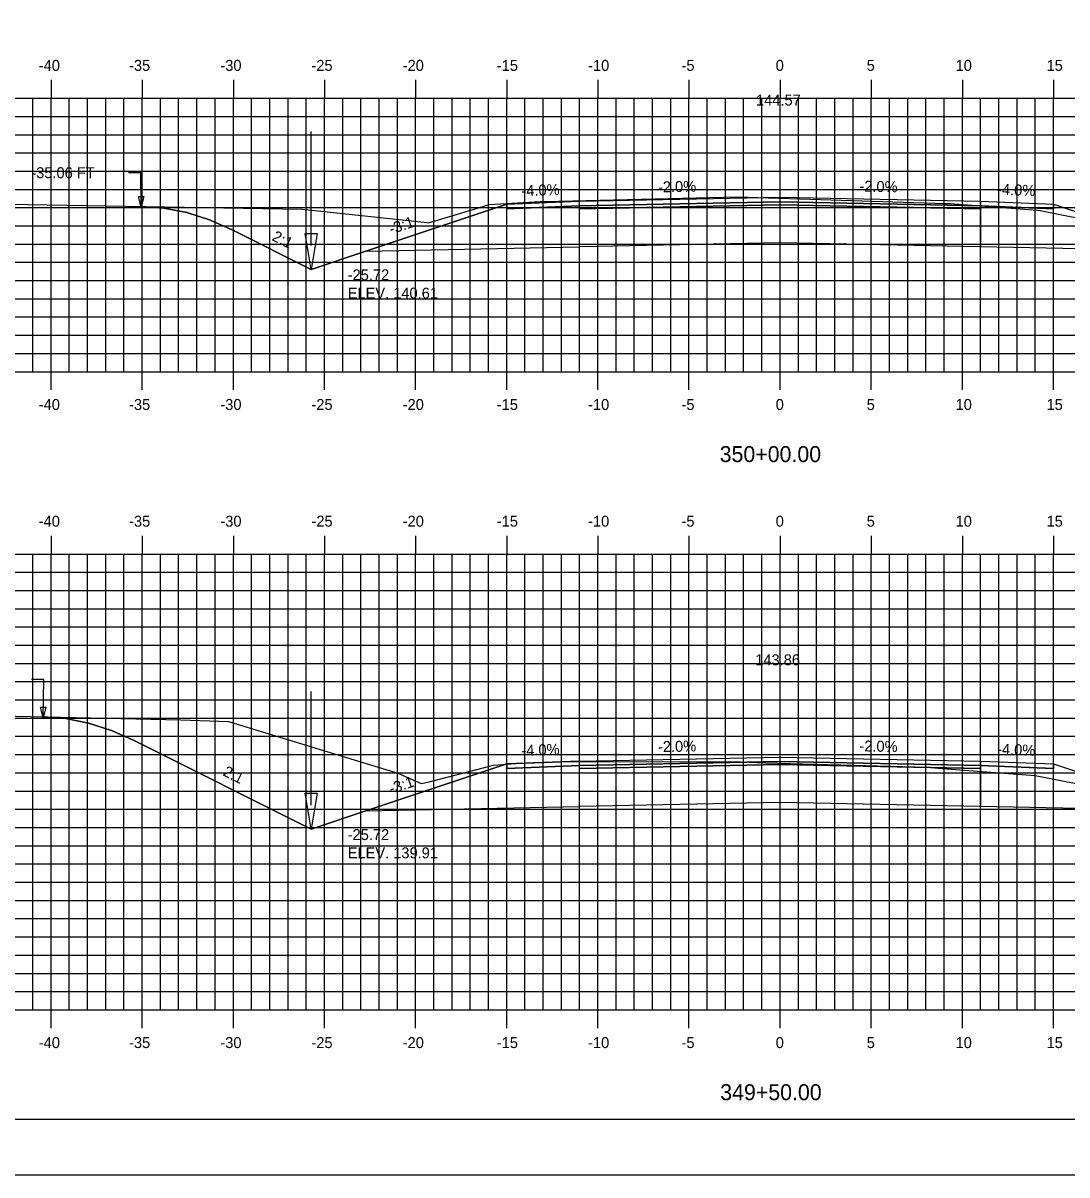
# Model space of a CAD drawing. Extents: x 1144529 to 1144699, y 608981 to 609091.
# Drawn here: x 1144570.3 to 1144627.6, y 608981.3 to 609044.5 of the extents above; entities that cross this region are included whole.
import ezdxf

# ---------------------------------------------------------------- set-up
doc = ezdxf.new("R2010")
doc.units = 0
for name, color, linetype in [('ANNOTATION', 7, 'Continuous'), ('BORDER', 7, 'Continuous'), ('D_Drainage_Ditch_Line', 7, 'Continuous'), ('D_Roadway_Centerline', 7, 'Continuous'), ('D_Roadway_Centerline_Text', 7, 'Continuous'), ('D_Roadway_Edge_Shoulder', 7, 'Continuous'), ('D_Roadway_Edge_TW', 7, 'Continuous'), ('D_Roadway_Pavement', 7, 'Continuous'), ('D_Roadway_SlopeLines', 7, 'Continuous'), ('D_Roadway_SubGrade', 7, 'Continuous'), ('D_Text_Standard', 7, 'Continuous'), ('H_V ANNOTATION', 7, 'Continuous'), ('MAJOR', 7, 'Continuous'), ('MINOR', 7, 'Continuous'), ('PLOT BOUNDARY', 7, 'Continuous'), ('S_Roadway_Centerline', 7, 'Continuous')]:
    doc.layers.add(name, color=color, linetype=linetype)

msp = doc.modelspace()

# ---------------------------------------------------------------- linework, layer by layer
for points in [[(1144576.807, 609034.403), (1144578.057, 609034.307), (1144579.307, 609034.059), (1144580.557, 609033.661), (1144581.807, 609033.112), (1144586.138, 609030.946), (1144589.138, 609031.946), (1144596.861, 609034.521), (1144596.862, 609034.521), (1144600.862, 609034.681), (1144611.862, 609034.901), (1144622.862, 609034.681), (1144626.862, 609034.521), (1144634.586, 609031.946), (1144637.586, 609030.946), (1144639.82, 609032.063), (1144641.07, 609032.601), (1144642.32, 609032.963), (1144643.57, 609033.15), (1144644.82, 609033.162)], [(1144571.423, 609006.407), (1144572.673, 609006.305), (1144573.923, 609006.053), (1144575.173, 609005.652), (1144576.423, 609005.102), (1144586.138, 609000.245), (1144589.138, 609001.245), (1144596.861, 609003.819), (1144596.862, 609003.819), (1144600.862, 609003.979), (1144611.862, 609004.199), (1144622.862, 609003.979), (1144626.862, 609003.819), (1144634.586, 609001.245), (1144637.586, 609000.245), (1144641.379, 609002.141), (1144642.629, 609002.679), (1144643.879, 609003.044), (1144645.129, 609003.234), (1144646.379, 609003.251)]]:
    msp.add_lwpolyline(points)
at = {"layer": 'BORDER'}
msp.add_lwpolyline([(1144536.863, 608984.335), (1144696.863, 608984.335), (1144696.863, 609089.335), (1144536.863, 609089.335)], close=True, dxfattribs=at)
at = {"layer": 'D_Drainage_Ditch_Line'}
for p, q in [((1144586.138, 609032.259), (1144586.138, 609038.502)), ((1144586.138, 609001.557), (1144586.138, 609007.801))]:
    msp.add_line(p, q, dxfattribs=at)
for points in [[(1144585.81, 609032.915), (1144586.466, 609032.915), (1144586.138, 609030.946)], [(1144585.81, 609002.213), (1144586.466, 609002.213), (1144586.138, 609000.245)]]:
    msp.add_lwpolyline(points, close=True, dxfattribs=at)
at = {"layer": 'D_Roadway_Edge_Shoulder'}
for points in [[(1144600.862, 609034.681), (1144596.862, 609034.521), (1144596.862, 609034.271), (1144600.862, 609034.431)], [(1144622.862, 609034.681), (1144626.862, 609034.521), (1144626.862, 609034.271), (1144622.862, 609034.431)], [(1144600.862, 609003.979), (1144596.862, 609003.819), (1144596.862, 609003.569), (1144600.862, 609003.729)], [(1144622.862, 609003.979), (1144626.862, 609003.819), (1144626.862, 609003.569), (1144622.862, 609003.729)]]:
    msp.add_lwpolyline(points, close=True, dxfattribs=at)
at = {"layer": 'D_Roadway_Edge_TW'}
for points in [[(1144600.862, 609034.431), (1144600.862, 609034.681), (1144611.862, 609034.901), (1144622.862, 609034.681), (1144622.862, 609034.431), (1144611.862, 609034.651)], [(1144600.862, 609003.729), (1144600.862, 609003.979), (1144611.862, 609004.199), (1144622.862, 609003.979), (1144622.862, 609003.729), (1144611.862, 609003.949)]]:
    msp.add_lwpolyline(points, close=True, dxfattribs=at)
at = {"layer": 'D_Roadway_Pavement'}
for points in [[(1144600.862, 609034.264), (1144600.862, 609034.431), (1144611.862, 609034.651), (1144622.862, 609034.431), (1144622.862, 609034.264), (1144611.862, 609034.484)], [(1144600.862, 609003.563), (1144600.862, 609003.729), (1144611.862, 609003.949), (1144622.862, 609003.729), (1144622.862, 609003.563), (1144611.862, 609003.783)]]:
    msp.add_lwpolyline(points, close=True, dxfattribs=at)
at = {"layer": 'D_Roadway_SlopeLines'}
for points in [[(1144586.138, 609030.946), (1144581.807, 609033.112), (1144580.557, 609033.661), (1144579.307, 609034.059), (1144578.057, 609034.307), (1144576.807, 609034.403)], [(1144589.138, 609031.946), (1144586.138, 609030.946)], [(1144586.138, 609000.245), (1144576.423, 609005.102), (1144575.173, 609005.652), (1144573.923, 609006.053), (1144572.673, 609006.305), (1144571.423, 609006.407)], [(1144589.138, 609001.245), (1144586.138, 609000.245)]]:
    msp.add_lwpolyline(points, dxfattribs=at)
at = {"layer": 'D_Roadway_SubGrade'}
for points in [[(1144600.862, 609034.264), (1144600.862, 609034.431), (1144596.862, 609034.271), (1144596.862, 609034.521), (1144596.861, 609034.521), (1144589.138, 609031.946), (1144600.862, 609032.181)], [(1144600.862, 609032.181), (1144600.862, 609034.264), (1144611.862, 609034.484), (1144622.862, 609034.264), (1144622.862, 609032.181), (1144611.862, 609032.401)], [(1144622.862, 609034.264), (1144622.862, 609034.431), (1144626.862, 609034.271), (1144626.862, 609034.521), (1144626.862, 609034.521), (1144634.586, 609031.946), (1144622.862, 609032.181)], [(1144600.862, 609003.563), (1144600.862, 609003.729), (1144596.862, 609003.569), (1144596.862, 609003.819), (1144596.861, 609003.819), (1144589.138, 609001.245), (1144600.862, 609001.479)], [(1144600.862, 609001.479), (1144600.862, 609003.563), (1144611.862, 609003.783), (1144622.862, 609003.563), (1144622.862, 609001.479), (1144611.862, 609001.699)], [(1144622.862, 609003.563), (1144622.862, 609003.729), (1144626.862, 609003.569), (1144626.862, 609003.819), (1144626.862, 609003.819), (1144634.586, 609001.245), (1144622.862, 609001.479)]]:
    msp.add_lwpolyline(points, close=True, dxfattribs=at)
at = {"layer": 'D_Text_Standard'}
for points in [[(1144576.807, 609034.362), (1144576.784, 609036.248), (1144576.104, 609036.248)], [(1144571.423, 609006.352), (1144571.464, 609008.455), (1144570.784, 609008.455)]]:
    msp.add_lwpolyline(points, dxfattribs=at)
for points in [[(1144576.807, 609034.362), (1144576.654, 609034.942), (1144576.945, 609034.945)], [(1144571.423, 609006.352), (1144571.289, 609006.937), (1144571.58, 609006.931)]]:
    msp.add_lwpolyline(points, close=True, dxfattribs=at)
at = {"layer": 'MAJOR'}
for p, q in [((1144571.862, 609041.337), (1144571.862, 609040.335)), ((1144576.862, 609041.337), (1144576.862, 609040.335)), ((1144581.862, 609041.337), (1144581.862, 609040.335)), ((1144586.862, 609041.337), (1144586.862, 609040.335)), ((1144591.862, 609041.337), (1144591.862, 609040.335)), ((1144596.862, 609041.337), (1144596.862, 609040.335)), ((1144601.862, 609041.337), (1144601.862, 609040.335)), ((1144606.862, 609041.337), (1144606.862, 609040.335)), ((1144611.862, 609041.337), (1144611.862, 609040.335)), ((1144616.862, 609041.337), (1144616.862, 609040.335)), ((1144621.862, 609041.337), (1144621.862, 609040.335)), ((1144626.862, 609041.337), (1144626.862, 609040.335)), ((1144541.862, 609040.335), (1144681.862, 609040.335)), ((1144541.862, 609040.335), (1144681.862, 609040.335)), ((1144571.862, 609025.335), (1144571.862, 609040.335)), ((1144576.862, 609025.335), (1144576.862, 609040.335)), ((1144581.862, 609025.335), (1144581.862, 609040.335)), ((1144586.862, 609025.335), (1144586.862, 609040.335)), ((1144591.862, 609025.335), (1144591.862, 609040.335)), ((1144596.862, 609025.335), (1144596.862, 609040.335)), ((1144601.862, 609025.335), (1144601.862, 609040.335)), ((1144606.862, 609025.335), (1144606.862, 609040.335)), ((1144611.862, 609025.335), (1144611.862, 609040.335)), ((1144616.862, 609025.335), (1144616.862, 609040.335)), ((1144621.862, 609025.335), (1144621.862, 609040.335)), ((1144626.862, 609025.335), (1144626.862, 609040.335)), ((1144541.862, 609035.335), (1144681.862, 609035.335)), ((1144541.862, 609030.335), (1144681.862, 609030.335)), ((1144541.862, 609025.335), (1144681.862, 609025.335)), ((1144541.862, 609025.335), (1144681.862, 609025.335)), ((1144571.862, 609024.333), (1144571.862, 609025.335)), ((1144576.862, 609024.333), (1144576.862, 609025.335)), ((1144581.862, 609024.333), (1144581.862, 609025.335)), ((1144586.862, 609024.333), (1144586.862, 609025.335)), ((1144591.862, 609024.333), (1144591.862, 609025.335)), ((1144596.862, 609024.333), (1144596.862, 609025.335)), ((1144601.862, 609024.333), (1144601.862, 609025.335)), ((1144606.862, 609024.333), (1144606.862, 609025.335)), ((1144611.862, 609024.333), (1144611.862, 609025.335)), ((1144616.862, 609024.333), (1144616.862, 609025.335)), ((1144621.862, 609024.333), (1144621.862, 609025.335)), ((1144626.862, 609024.333), (1144626.862, 609025.335)), ((1144571.862, 609016.337), (1144571.862, 609015.335)), ((1144576.862, 609016.337), (1144576.862, 609015.335)), ((1144581.862, 609016.337), (1144581.862, 609015.335)), ((1144586.862, 609016.337), (1144586.862, 609015.335)), ((1144591.862, 609016.337), (1144591.862, 609015.335)), ((1144596.862, 609016.337), (1144596.862, 609015.335)), ((1144601.862, 609016.337), (1144601.862, 609015.335)), ((1144606.862, 609016.337), (1144606.862, 609015.335)), ((1144611.862, 609016.337), (1144611.862, 609015.335)), ((1144616.862, 609016.337), (1144616.862, 609015.335)), ((1144621.862, 609016.337), (1144621.862, 609015.335)), ((1144626.862, 609016.337), (1144626.862, 609015.335)), ((1144541.862, 609015.335), (1144681.862, 609015.335)), ((1144541.862, 609015.335), (1144681.862, 609015.335)), ((1144571.862, 608990.335), (1144571.862, 609015.335)), ((1144576.862, 608990.335), (1144576.862, 609015.335)), ((1144581.862, 608990.335), (1144581.862, 609015.335)), ((1144586.862, 608990.335), (1144586.862, 609015.335)), ((1144591.862, 608990.335), (1144591.862, 609015.335)), ((1144596.862, 608990.335), (1144596.862, 609015.335)), ((1144601.862, 608990.335), (1144601.862, 609015.335)), ((1144606.862, 608990.335), (1144606.862, 609015.335)), ((1144611.862, 608990.335), (1144611.862, 609015.335)), ((1144616.862, 608990.335), (1144616.862, 609015.335)), ((1144621.862, 608990.335), (1144621.862, 609015.335)), ((1144626.862, 608990.335), (1144626.862, 609015.335)), ((1144541.862, 609010.335), (1144681.862, 609010.335)), ((1144541.862, 609005.335), (1144681.862, 609005.335)), ((1144541.862, 609000.335), (1144681.862, 609000.335)), ((1144541.862, 608995.335), (1144681.862, 608995.335)), ((1144541.862, 608990.335), (1144681.862, 608990.335)), ((1144541.862, 608990.335), (1144681.862, 608990.335)), ((1144571.862, 608989.333), (1144571.862, 608990.335)), ((1144576.862, 608989.333), (1144576.862, 608990.335)), ((1144581.862, 608989.333), (1144581.862, 608990.335)), ((1144586.862, 608989.333), (1144586.862, 608990.335)), ((1144591.862, 608989.333), (1144591.862, 608990.335)), ((1144596.862, 608989.333), (1144596.862, 608990.335)), ((1144601.862, 608989.333), (1144601.862, 608990.335)), ((1144606.862, 608989.333), (1144606.862, 608990.335)), ((1144611.862, 608989.333), (1144611.862, 608990.335)), ((1144616.862, 608989.333), (1144616.862, 608990.335)), ((1144621.862, 608989.333), (1144621.862, 608990.335)), ((1144626.862, 608989.333), (1144626.862, 608990.335))]:
    msp.add_line(p, q, dxfattribs=at)
at = {"layer": 'MINOR'}
for p, q in [((1144570.862, 609025.335), (1144570.862, 609040.335)), ((1144572.862, 609025.335), (1144572.862, 609040.335)), ((1144573.862, 609025.335), (1144573.862, 609040.335)), ((1144574.862, 609025.335), (1144574.862, 609040.335)), ((1144575.862, 609025.335), (1144575.862, 609040.335)), ((1144577.862, 609025.335), (1144577.862, 609040.335)), ((1144578.862, 609025.335), (1144578.862, 609040.335)), ((1144579.862, 609025.335), (1144579.862, 609040.335)), ((1144580.862, 609025.335), (1144580.862, 609040.335)), ((1144582.862, 609025.335), (1144582.862, 609040.335)), ((1144583.862, 609025.335), (1144583.862, 609040.335)), ((1144584.862, 609025.335), (1144584.862, 609040.335)), ((1144585.862, 609025.335), (1144585.862, 609040.335)), ((1144587.862, 609025.335), (1144587.862, 609040.335)), ((1144588.862, 609025.335), (1144588.862, 609040.335)), ((1144589.862, 609025.335), (1144589.862, 609040.335)), ((1144590.862, 609025.335), (1144590.862, 609040.335)), ((1144592.862, 609025.335), (1144592.862, 609040.335)), ((1144593.862, 609025.335), (1144593.862, 609040.335)), ((1144594.862, 609025.335), (1144594.862, 609040.335)), ((1144595.862, 609025.335), (1144595.862, 609040.335)), ((1144597.862, 609025.335), (1144597.862, 609040.335)), ((1144598.862, 609025.335), (1144598.862, 609040.335)), ((1144599.862, 609025.335), (1144599.862, 609040.335)), ((1144600.862, 609025.335), (1144600.862, 609040.335)), ((1144602.862, 609025.335), (1144602.862, 609040.335)), ((1144603.862, 609025.335), (1144603.862, 609040.335)), ((1144604.862, 609025.335), (1144604.862, 609040.335)), ((1144605.862, 609025.335), (1144605.862, 609040.335)), ((1144607.862, 609025.335), (1144607.862, 609040.335)), ((1144608.862, 609025.335), (1144608.862, 609040.335)), ((1144609.862, 609025.335), (1144609.862, 609040.335)), ((1144610.862, 609025.335), (1144610.862, 609040.335)), ((1144612.862, 609025.335), (1144612.862, 609040.335)), ((1144613.862, 609025.335), (1144613.862, 609040.335)), ((1144614.862, 609025.335), (1144614.862, 609040.335)), ((1144615.862, 609025.335), (1144615.862, 609040.335)), ((1144617.862, 609025.335), (1144617.862, 609040.335)), ((1144618.862, 609025.335), (1144618.862, 609040.335)), ((1144619.862, 609025.335), (1144619.862, 609040.335)), ((1144620.862, 609025.335), (1144620.862, 609040.335)), ((1144622.862, 609025.335), (1144622.862, 609040.335)), ((1144623.862, 609025.335), (1144623.862, 609040.335)), ((1144624.862, 609025.335), (1144624.862, 609040.335)), ((1144625.862, 609025.335), (1144625.862, 609040.335)), ((1144541.862, 609039.335), (1144681.862, 609039.335)), ((1144541.862, 609038.335), (1144681.862, 609038.335)), ((1144541.862, 609037.335), (1144681.862, 609037.335)), ((1144541.862, 609036.335), (1144681.862, 609036.335)), ((1144541.862, 609034.335), (1144681.862, 609034.335)), ((1144541.862, 609033.335), (1144681.862, 609033.335)), ((1144541.862, 609032.335), (1144681.862, 609032.335)), ((1144541.862, 609031.335), (1144681.862, 609031.335)), ((1144541.862, 609029.335), (1144681.862, 609029.335)), ((1144541.862, 609028.335), (1144681.862, 609028.335)), ((1144541.862, 609027.335), (1144681.862, 609027.335)), ((1144541.862, 609026.335), (1144681.862, 609026.335)), ((1144570.862, 608990.335), (1144570.862, 609015.335)), ((1144572.862, 608990.335), (1144572.862, 609015.335)), ((1144573.862, 608990.335), (1144573.862, 609015.335)), ((1144574.862, 608990.335), (1144574.862, 609015.335)), ((1144575.862, 608990.335), (1144575.862, 609015.335)), ((1144577.862, 608990.335), (1144577.862, 609015.335)), ((1144578.862, 608990.335), (1144578.862, 609015.335)), ((1144579.862, 608990.335), (1144579.862, 609015.335)), ((1144580.862, 608990.335), (1144580.862, 609015.335)), ((1144582.862, 608990.335), (1144582.862, 609015.335)), ((1144583.862, 608990.335), (1144583.862, 609015.335)), ((1144584.862, 608990.335), (1144584.862, 609015.335)), ((1144585.862, 608990.335), (1144585.862, 609015.335)), ((1144587.862, 608990.335), (1144587.862, 609015.335)), ((1144588.862, 608990.335), (1144588.862, 609015.335)), ((1144589.862, 608990.335), (1144589.862, 609015.335)), ((1144590.862, 608990.335), (1144590.862, 609015.335)), ((1144592.862, 608990.335), (1144592.862, 609015.335)), ((1144593.862, 608990.335), (1144593.862, 609015.335)), ((1144594.862, 608990.335), (1144594.862, 609015.335)), ((1144595.862, 608990.335), (1144595.862, 609015.335)), ((1144597.862, 608990.335), (1144597.862, 609015.335)), ((1144598.862, 608990.335), (1144598.862, 609015.335)), ((1144599.862, 608990.335), (1144599.862, 609015.335)), ((1144600.862, 608990.335), (1144600.862, 609015.335)), ((1144602.862, 608990.335), (1144602.862, 609015.335)), ((1144603.862, 608990.335), (1144603.862, 609015.335)), ((1144604.862, 608990.335), (1144604.862, 609015.335)), ((1144605.862, 608990.335), (1144605.862, 609015.335)), ((1144607.862, 608990.335), (1144607.862, 609015.335)), ((1144608.862, 608990.335), (1144608.862, 609015.335)), ((1144609.862, 608990.335), (1144609.862, 609015.335)), ((1144610.862, 608990.335), (1144610.862, 609015.335)), ((1144612.862, 608990.335), (1144612.862, 609015.335)), ((1144613.862, 608990.335), (1144613.862, 609015.335)), ((1144614.862, 608990.335), (1144614.862, 609015.335)), ((1144615.862, 608990.335), (1144615.862, 609015.335)), ((1144617.862, 608990.335), (1144617.862, 609015.335)), ((1144618.862, 608990.335), (1144618.862, 609015.335)), ((1144619.862, 608990.335), (1144619.862, 609015.335)), ((1144620.862, 608990.335), (1144620.862, 609015.335)), ((1144622.862, 608990.335), (1144622.862, 609015.335)), ((1144623.862, 608990.335), (1144623.862, 609015.335)), ((1144624.862, 608990.335), (1144624.862, 609015.335)), ((1144625.862, 608990.335), (1144625.862, 609015.335)), ((1144541.862, 609014.335), (1144681.862, 609014.335)), ((1144541.862, 609013.335), (1144681.862, 609013.335)), ((1144541.862, 609012.335), (1144681.862, 609012.335)), ((1144541.862, 609011.335), (1144681.862, 609011.335)), ((1144541.862, 609009.335), (1144681.862, 609009.335)), ((1144541.862, 609008.335), (1144681.862, 609008.335)), ((1144541.862, 609007.335), (1144681.862, 609007.335)), ((1144541.862, 609006.335), (1144681.862, 609006.335)), ((1144541.862, 609004.335), (1144681.862, 609004.335)), ((1144541.862, 609003.335), (1144681.862, 609003.335)), ((1144541.862, 609002.335), (1144681.862, 609002.335)), ((1144541.862, 609001.335), (1144681.862, 609001.335)), ((1144541.862, 608999.335), (1144681.862, 608999.335)), ((1144541.862, 608998.335), (1144681.862, 608998.335)), ((1144541.862, 608997.335), (1144681.862, 608997.335)), ((1144541.862, 608996.335), (1144681.862, 608996.335)), ((1144541.862, 608994.335), (1144681.862, 608994.335)), ((1144541.862, 608993.335), (1144681.862, 608993.335)), ((1144541.862, 608992.335), (1144681.862, 608992.335)), ((1144541.862, 608991.335), (1144681.862, 608991.335))]:
    msp.add_line(p, q, dxfattribs=at)
at = {"layer": 'PLOT BOUNDARY'}
msp.add_lwpolyline([(1144528.769, 608981.276), (1144698.769, 608981.276), (1144698.769, 609091.276), (1144528.769, 609091.276)], close=True, dxfattribs=at)
at = {"layer": 'S_Roadway_Centerline'}
for points in [[(1144561.666, 609034.654), (1144561.946, 609034.651), (1144585.646, 609034.256), (1144592.503, 609033.516), (1144592.567, 609033.501), (1144595.079, 609034.252), (1144595.9, 609034.497), (1144595.906, 609034.498), (1144598.704, 609034.678), (1144598.944, 609034.678), (1144609.518, 609034.918), (1144620.904, 609034.561), (1144621.236, 609034.553), (1144621.437, 609034.537), (1144625.991, 609034.203), (1144626.131, 609034.175), (1144629.717, 609033.462), (1144631.943, 609033.887), (1144632.107, 609033.929), (1144632.595, 609033.902), (1144655.776, 609032.498)], [(1144559.187, 609006.676), (1144578.978, 609006.241), (1144581.605, 609006.146), (1144590.889, 609003.306), (1144592.175, 609002.739), (1144592.604, 609002.838), (1144596.133, 609003.761), (1144597.846, 609003.878), (1144598.337, 609003.906), (1144599.767, 609003.934), (1144609.205, 609003.954), (1144611.065, 609003.88), (1144619.958, 609003.648), (1144620.511, 609003.593), (1144625.858, 609003.18), (1144626.506, 609003.065), (1144628.858, 609002.594), (1144634.039, 609003.929), (1144635.609, 609003.813), (1144637.17, 609003.769), (1144654.147, 609002.813), (1144656.428, 609002.61), (1144659.014, 609002.64)]]:
    msp.add_lwpolyline(points, dxfattribs=at)

# ---------------------------------------------------------------- texts
at = {"layer": 'ANNOTATION'}
for s, rotation, p in [('-4.0%', 2.29061, (1144597.678, 609034.954)), ('-2.0%', 1.14576, (1144605.165, 609035.167)), ('-2.0%', 358.85424, (1144616.205, 609035.214)), ('-4.0%', 357.70939, (1144623.758, 609035.046)), ('-3:1', 18.43482, (1144590.517, 609032.86)), ('2:1', 333.43495, (1144583.939, 609032.563)), ('-2.0%', 1.14576, (1144605.165, 609004.466)), ('-2.0%', 358.85424, (1144616.205, 609004.513)), ('-4.0%', 2.29061, (1144597.678, 609004.253)), ('-4.0%', 357.70939, (1144623.758, 609004.344)), ('2:1', 333.43495, (1144581.248, 609003.208)), ('-3:1', 18.43482, (1144590.517, 609002.159))]:
    msp.add_text(s, height=0.6, rotation=rotation, dxfattribs=at).set_placement(p)
at = {"layer": 'D_Roadway_Centerline'}
for s, p in [('C', (1144611.857, 609034.901)), ('L', (1144611.862, 609034.894)), ('C', (1144611.857, 609004.199)), ('L', (1144611.862, 609004.192))]:
    msp.add_text(s, height=0.0146, dxfattribs=at).set_placement(p)
at = {"layer": 'D_Roadway_Centerline_Text'}
for s, p in [('144.57', (1144610.541, 609039.933)), ('143.86', (1144610.498, 609009.231))]:
    msp.add_text(s, height=0.6, dxfattribs=at).set_placement(p)
at = {"layer": 'D_Text_Standard'}
for s, p in [('-35.06 FT', (1144570.777, 609035.948)), ('-25.72', (1144588.138, 609030.346)), ('ELEV. 140.61', (1144588.138, 609029.344)), ('-25.72', (1144588.138, 608999.645)), ('ELEV. 139.91', (1144588.138, 608998.643))]:
    msp.add_text(s, height=0.6, dxfattribs=at).set_placement(p)
at = {"layer": 'H_V ANNOTATION'}
for s, height, p in [('-40', 0.6, (1144571.188, 609041.835)), ('-35', 0.6, (1144576.143, 609041.835)), ('-30', 0.6, (1144581.151, 609041.835)), ('-25', 0.6, (1144586.148, 609041.835)), ('-20', 0.6, (1144591.156, 609041.835)), ('-15', 0.6, (1144596.319, 609041.835)), ('-10', 0.6, (1144601.327, 609041.835)), ('-5', 0.6, (1144606.453, 609041.835)), ('0', 0.6, (1144611.621, 609041.835)), ('5', 0.6, (1144616.613, 609041.835)), ('10', 0.6, (1144621.488, 609041.835)), ('15', 0.6, (1144626.48, 609041.835)), ('-40', 0.6, (1144571.188, 609023.235)), ('-35', 0.6, (1144576.143, 609023.235)), ('-30', 0.6, (1144581.151, 609023.235)), ('-25', 0.6, (1144586.148, 609023.235)), ('-20', 0.6, (1144591.156, 609023.235)), ('-15', 0.6, (1144596.319, 609023.235)), ('-10', 0.6, (1144601.327, 609023.235)), ('-5', 0.6, (1144606.453, 609023.235)), ('0', 0.6, (1144611.621, 609023.235)), ('5', 0.6, (1144616.613, 609023.235)), ('10', 0.6, (1144621.488, 609023.235)), ('15', 0.6, (1144626.48, 609023.235)), ('350+00.00', 0.875, (1144608.546, 609020.378)), ('-40', 0.6, (1144571.188, 609016.835)), ('-35', 0.6, (1144576.143, 609016.835)), ('-30', 0.6, (1144581.151, 609016.835)), ('-25', 0.6, (1144586.148, 609016.835)), ('-20', 0.6, (1144591.156, 609016.835)), ('-15', 0.6, (1144596.319, 609016.835)), ('-10', 0.6, (1144601.327, 609016.835)), ('-5', 0.6, (1144606.453, 609016.835)), ('0', 0.6, (1144611.621, 609016.835)), ('5', 0.6, (1144616.613, 609016.835)), ('10', 0.6, (1144621.488, 609016.835)), ('15', 0.6, (1144626.48, 609016.835)), ('-40', 0.6, (1144571.188, 608988.235)), ('-35', 0.6, (1144576.143, 608988.235)), ('-30', 0.6, (1144581.151, 608988.235)), ('-25', 0.6, (1144586.148, 608988.235)), ('-20', 0.6, (1144591.156, 608988.235)), ('-15', 0.6, (1144596.319, 608988.235)), ('-10', 0.6, (1144601.327, 608988.235)), ('-5', 0.6, (1144606.453, 608988.235)), ('0', 0.6, (1144611.621, 608988.235)), ('5', 0.6, (1144616.613, 608988.235)), ('10', 0.6, (1144621.488, 608988.235)), ('15', 0.6, (1144626.48, 608988.235)), ('349+50.00', 0.875, (1144608.577, 608985.378))]:
    msp.add_text(s, height=height, dxfattribs=at).set_placement(p)
at = {"layer": 'S_Roadway_Centerline'}
for s, p in [('L', (1144609.51, 609034.911)), ('C', (1144609.513, 609034.918)), ('L', (1144609.197, 609003.947)), ('C', (1144609.2, 609003.954))]:
    msp.add_text(s, height=0.0146, dxfattribs=at).set_placement(p)

doc.saveas('drawing.dxf')
